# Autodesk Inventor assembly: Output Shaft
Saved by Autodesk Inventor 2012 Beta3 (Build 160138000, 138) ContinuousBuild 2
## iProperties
Created: 2011-01
Part Number: Output Shaft
Document SubType Name: Assembly
Designer: Beta-8540w
ClientObjectVersion: 1
Author: Beta-8540w
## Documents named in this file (2)
- C:\Inventor 2012 Essentials\Assemblies\Chapter 8\Design Accelerators\Shaft c8-02.iam
- C:\Inventor 2012 Essentials\Assemblies\Chapter 8\Design Accelerators\Shaft c8-02.ipt
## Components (1 placed, 1 different names)
1. Output Shaft:1
